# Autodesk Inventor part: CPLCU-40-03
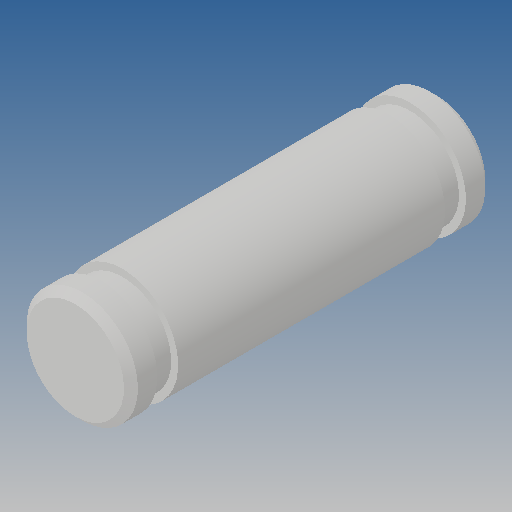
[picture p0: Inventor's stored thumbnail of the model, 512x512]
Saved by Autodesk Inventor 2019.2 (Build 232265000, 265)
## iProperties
Created: 2010-03
Part Number: CPLCU-40-03
Material: Ogólny
Document SubType Name: Modeling
Designer: CADENGINEERING4
Density: 1 g/cm^3
Appearance: Domyślna
Author: CADENGINEERING4
Revision Number: 2LAST_VERSION
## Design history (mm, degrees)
feature "Baza1"
node "Bryła1"
